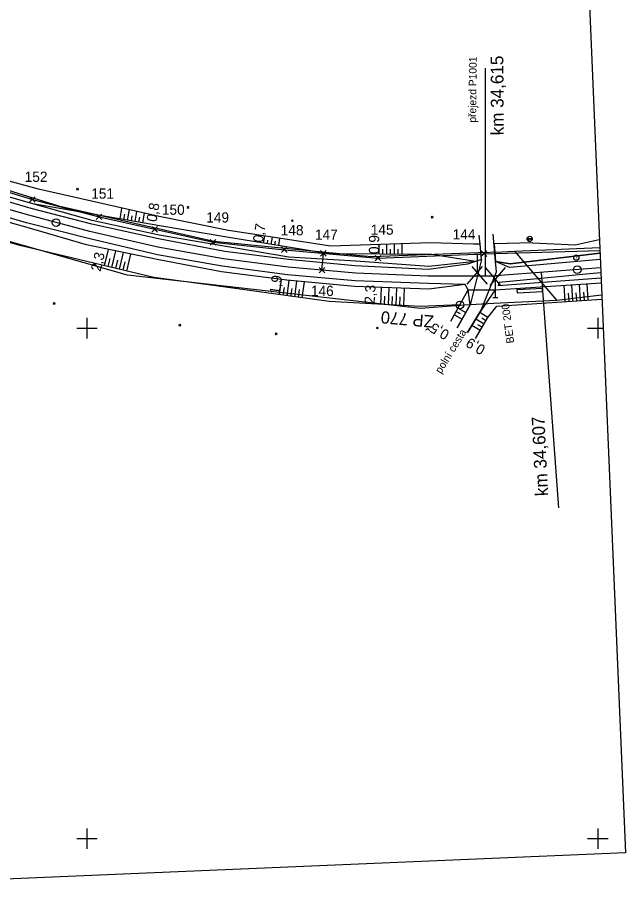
# Model space of a CAD drawing. Extents: x -806456 to -805395, y -1150847 to -1150506.
# Drawn here: x -805513.6 to -805394.6, y -1150811.7 to -1150639.2 of the extents above; entities that cross this region are included whole.
import ezdxf

# ---------------------------------------------------------------- set-up
doc = ezdxf.new("R2010")
doc.units = 0
for name, color, linetype in [('0381KM032-037P - Vrstva 1', 7, 'Continuous'), ('0381KM032-037P - Vrstva 19', 7, 'Continuous'), ('0381KM032-037P - Vrstva 36', 7, 'Continuous'), ('0381KM032-037P - Vrstva 4', 7, 'Continuous'), ('0381KM032-037P - Vrstva 48', 7, 'Continuous'), ('0381KM032-037P - Vrstva 49', 7, 'Continuous'), ('0381KM032-037P - Vrstva 51', 7, 'Continuous'), ('0381KM032-037P - Vrstva 55', 7, 'Continuous'), ('0381KM032-037P - Vrstva 7', 7, 'Continuous'), ('0381KM032-037P - Vrstva 9', 7, 'Continuous'), ('Default', 7, 'Continuous'), ('formát', 7, 'Continuous'), ('hran DP - hran DP', 7, 'Continuous'), ('krizky_1000 - Vrstva 1', 7, 'Continuous'), ('PSR_C2_2_Lomove_body_Vimperk - Vrstva 60', 7, 'Continuous'), ('PSR_C2_2_trasa_Vimperk - Kabelová trasa', 7, 'Continuous'), ('vyt_sit - stávající', 7, 'Continuous')]:
    doc.layers.add(name, color=color, linetype=linetype)

msp = doc.modelspace()

# ---------------------------------------------------------------- linework, layer by layer
at = {"layer": '0381KM032-037P - Vrstva 1'}
for points in [[(-805499.4, -1150681.08), (-805511.35, -1150677.89), (-805524.48, -1150674.12), (-805529.81, -1150672.54)], [(-805399.47, -1150688.2), (-805419.96, -1150689.78), (-805423.96, -1150689.8), (-805433.29, -1150689.8), (-805447.38, -1150689.21), (-805460.61, -1150688.07), (-805473.24, -1150686.41), (-805486.12, -1150684.11), (-805499.4, -1150681.08)]]:
    msp.add_lwpolyline(points, dxfattribs=at)
at = {"layer": '0381KM032-037P - Vrstva 19'}
msp.add_line((-805425.41, -1150692.47), (-805420.07, -1150692.47), dxfattribs=at)
at = {"layer": '0381KM032-037P - Vrstva 36'}
for p, q in [((-805413.84, -1150682.5), (-805412.84, -1150682.5)), ((-805412.84, -1150682.5), (-805413.84, -1150682.5)), ((-805413.28, -1150683), (-805413.77, -1150682.5)), ((-805412.94, -1150682.8), (-805413.24, -1150682.5))]:
    msp.add_line(p, q, dxfattribs=at)
msp.add_circle((-805413.34, -1150682.5), 0.503, dxfattribs=at)
msp.add_arc((-805413.34, -1150682.5), 0.503, 180, 0, dxfattribs=at)
at = {"layer": '0381KM032-037P - Vrstva 4'}
for p, q in [((-805421.99, -1150689.77), (-805421.99, -1150649.07)), ((-805423.11, -1150685.55), (-805424.11, -1150685.55)), ((-805423.61, -1150685.55), (-805423.61, -1150689.05)), ((-805422.61, -1150687.9), (-805425.61, -1150691.4)), ((-805421.61, -1150691.4), (-805424.61, -1150687.9)), ((-805422.05, -1150688.15), (-805419.05, -1150691.65)), ((-805421.05, -1150691.65), (-805418.05, -1150688.15)), ((-805423.96, -1150689.8), (-805419.82, -1150689.74)), ((-805420.05, -1150694), (-805420.05, -1150690.5)), ((-805420.55, -1150694), (-805419.55, -1150694))]:
    msp.add_line(p, q, dxfattribs=at)
for points in [[(-805485.85, -1150681.76), (-805498.96, -1150678.92), (-805510.6, -1150675.66), (-805525.22, -1150671.48), (-805544.53, -1150665.72), (-805562.31, -1150661.11), (-805574.56, -1150658.15), (-805590.74, -1150655.42), (-805602.22, -1150654.14), (-805617.62, -1150652.74), (-805630.08, -1150651.83), (-805647.65, -1150650.8), (-805688.26, -1150650.5)], [(-805423.97, -1150686.92), (-805425.51, -1150687.49), (-805433.17, -1150688.49), (-805447.58, -1150687.79), (-805460.54, -1150686.52), (-805473.03, -1150684.97), (-805486, -1150682.53), (-805499.06, -1150679.64), (-805510.93, -1150676.58), (-805525.41, -1150672.29), (-805545.14, -1150666.47), (-805562.36, -1150661.85), (-805574.71, -1150659.28), (-805590.7, -1150656.46), (-805602.42, -1150654.96), (-805617.57, -1150653.8), (-805630.08, -1150653.28), (-805647.6, -1150652.35), (-805687.98, -1150651.47)], [(-805425.98, -1150691.47), (-805433.13, -1150691.22), (-805447.47, -1150690.71), (-805460.74, -1150689.57), (-805473.54, -1150687.87), (-805486.2, -1150685.62), (-805499.7, -1150682.42), (-805511.82, -1150679.35), (-805526.11, -1150675.23), (-805545.84, -1150669.48), (-805563.16, -1150664.96), (-805575.57, -1150662.2), (-805590.62, -1150659.46), (-805602.86, -1150658.06), (-805617.64, -1150656.78), (-805630.16, -1150656.16), (-805647.73, -1150655.65), (-805688.15, -1150654.42)], [(-805425.41, -1150692.47), (-805425.98, -1150691.47), (-805433.11, -1150692.35), (-805447.61, -1150691.82), (-805460.9, -1150690.59), (-805473.67, -1150688.98), (-805486.26, -1150686.57), (-805500.08, -1150683.65), (-805512.15, -1150680.12), (-805526.27, -1150676.26), (-805545.98, -1150670.57), (-805563.42, -1150665.87), (-805575.79, -1150663.12), (-805590.93, -1150660.59), (-805603.28, -1150659.09), (-805617.92, -1150657.97), (-805630.11, -1150657.32), (-805646.66, -1150657.1), (-805648.58, -1150657.2), (-805687.42, -1150655.93)], [(-805423.97, -1150686.92), (-805433.1, -1150687.91), (-805447.34, -1150686.91), (-805460.49, -1150686.09), (-805485.85, -1150681.76)], [(-805399.6, -1150685.34), (-805417.14, -1150687.42), (-805420, -1150686.97)], [(-805399.54, -1150686.56), (-805417.27, -1150688.09), (-805420, -1150686.97)], [(-805399.43, -1150689.16), (-805401.63, -1150689.36), (-805419.33, -1150691.07), (-805419.49, -1150691.68)], [(-805399.39, -1150690.24), (-805419.49, -1150691.68)]]:
    msp.add_lwpolyline(points, dxfattribs=at)
at = {"layer": '0381KM032-037P - Vrstva 48'}
for p, q in [((-805493.52, -1150678.6), (-805493.15, -1150676.49)), ((-805492.78, -1150678.73), (-805492.6, -1150677.69)), ((-805492.04, -1150678.85), (-805491.69, -1150676.82)), ((-805491.3, -1150678.98), (-805491.13, -1150677.99)), ((-805490.56, -1150679.11), (-805490.22, -1150677.16)), ((-805489.82, -1150679.23), (-805489.66, -1150678.28)), ((-805489.08, -1150679.36), (-805488.76, -1150677.49)), ((-805465.41, -1150683.34), (-805465.19, -1150681.94)), ((-805464.67, -1150683.46), (-805464.56, -1150682.75)), ((-805463.93, -1150683.58), (-805463.7, -1150682.16)), ((-805463.19, -1150683.7), (-805463.07, -1150682.98)), ((-805462.45, -1150683.82), (-805462.22, -1150682.37)), ((-805441.32, -1150685.5), (-805441.3, -1150683.55)), ((-805439.82, -1150685.51), (-805439.8, -1150683.51)), ((-805438.32, -1150685.52), (-805438.3, -1150683.46)), ((-805496.56, -1150687.78), (-805495.8, -1150684.56)), ((-805495.1, -1150688.12), (-805494.33, -1150684.87)), ((-805493.64, -1150688.47), (-805492.86, -1150685.18)), ((-805442.82, -1150685.49), (-805442.8, -1150683.6)), ((-805442.07, -1150685.49), (-805442.06, -1150684.53)), ((-805440.57, -1150685.5), (-805440.56, -1150684.52)), ((-805439.07, -1150685.51), (-805439.06, -1150684.5)), ((-805495.83, -1150687.95), (-805495.45, -1150686.33)), ((-805494.37, -1150688.3), (-805493.98, -1150686.66)), ((-805492.91, -1150688.64), (-805492.52, -1150686.99)), ((-805492.18, -1150688.82), (-805491.39, -1150685.49)), ((-805462.31, -1150693.46), (-805461.89, -1150690.47)), ((-805461.56, -1150693.56), (-805461.35, -1150692.06)), ((-805460.82, -1150693.66), (-805460.4, -1150690.64)), ((-805459.33, -1150693.87), (-805458.91, -1150690.78)), ((-805457.85, -1150694.07), (-805457.41, -1150690.91)), ((-805442.5, -1150695.34), (-805442.32, -1150692.01)), ((-805441, -1150695.43), (-805440.82, -1150692.07)), ((-805439.5, -1150695.51), (-805439.32, -1150692.12)), ((-805438, -1150695.59), (-805437.82, -1150692.18)), ((-805406.38, -1150694.81), (-805406.59, -1150691.59)), ((-805404.88, -1150694.71), (-805405.09, -1150691.49)), ((-805403.39, -1150694.62), (-805403.59, -1150691.39)), ((-805401.89, -1150694.52), (-805402.09, -1150691.3)), ((-805460.08, -1150693.77), (-805459.86, -1150692.24)), ((-805458.59, -1150693.97), (-805458.38, -1150692.41)), ((-805441.75, -1150695.39), (-805441.66, -1150693.71)), ((-805440.25, -1150695.47), (-805440.16, -1150693.78)), ((-805438.75, -1150695.55), (-805438.66, -1150693.85)), ((-805405.63, -1150694.76), (-805405.73, -1150693.15)), ((-805404.13, -1150694.66), (-805404.24, -1150693.05)), ((-805402.64, -1150694.57), (-805402.74, -1150692.96)), ((-805428.08, -1150697.36), (-805426.58, -1150698.22)), ((-805427.71, -1150696.71), (-805426.96, -1150697.14)), ((-805427.34, -1150696.06), (-805425.83, -1150696.92)), ((-805421.51, -1150697.9), (-805423.11, -1150696.95)), ((-805422.27, -1150699.19), (-805423.9, -1150698.22)), ((-805421.89, -1150698.54), (-805422.7, -1150698.06)), ((-805423.04, -1150700.48), (-805424.68, -1150699.5)), ((-805422.66, -1150699.83), (-805423.47, -1150699.35))]:
    msp.add_line(p, q, dxfattribs=at)
at = {"layer": '0381KM032-037P - Vrstva 49'}
for p, q in [((-805501.66, -1150672.97), (-805502.01, -1150672.62)), ((-805501.66, -1150672.62), (-805502.01, -1150672.97)), ((-805480.06, -1150676.54), (-805480.41, -1150676.19)), ((-805480.06, -1150676.19), (-805480.41, -1150676.54)), ((-805432.26, -1150678.45), (-805432.61, -1150678.1)), ((-805432.26, -1150678.1), (-805432.61, -1150678.45)), ((-805459.62, -1150679.12), (-805459.97, -1150678.77)), ((-805459.62, -1150678.77), (-805459.97, -1150679.12)), ((-805426.99, -1150695.45), (-805425.41, -1150692.47)), ((-805506.23, -1150695.39), (-805506.58, -1150695.03)), ((-805506.23, -1150695.03), (-805506.58, -1150695.39)), ((-805481.65, -1150699.61), (-805482, -1150699.26)), ((-805481.65, -1150699.26), (-805482, -1150699.61)), ((-805442.98, -1150700.16), (-805443.33, -1150699.81)), ((-805442.98, -1150699.81), (-805443.33, -1150700.16)), ((-805462.79, -1150701.28), (-805463.14, -1150700.93)), ((-805462.79, -1150700.93), (-805463.14, -1150701.28))]:
    msp.add_line(p, q, dxfattribs=at)
for points in [[(-805423.97, -1150686.92), (-805433.1, -1150687.91), (-805447.34, -1150686.91), (-805460.49, -1150686.09), (-805485.85, -1150681.76), (-805498.96, -1150678.92), (-805510.6, -1150675.66), (-805525.22, -1150671.48), (-805544.53, -1150665.72), (-805562.31, -1150661.11), (-805571.99, -1150658.79), (-805574.56, -1150658.15), (-805590.74, -1150655.42), (-805602.22, -1150654.14), (-805617.62, -1150652.74), (-805630.08, -1150651.83), (-805647.65, -1150650.8), (-805688.26, -1150650.5)], [(-805424.36, -1150683.57), (-805432.74, -1150683.28), (-805452.35, -1150683.91), (-805462.43, -1150682.34), (-805472.3, -1150680.9), (-805485.84, -1150678.15), (-805509.51, -1150672.79), (-805524.62, -1150668.67), (-805544.15, -1150662.92), (-805562.19, -1150658.51), (-805574.34, -1150655.56), (-805587.56, -1150653.68), (-805602.19, -1150651.94)], [(-805425.41, -1150692.47), (-805425.98, -1150691.47), (-805433.11, -1150692.35), (-805447.61, -1150691.82), (-805460.9, -1150690.59), (-805473.67, -1150688.98), (-805486.26, -1150686.57), (-805500.08, -1150683.65), (-805512.15, -1150680.12), (-805526.27, -1150676.26), (-805545.98, -1150670.57), (-805563.42, -1150665.87), (-805575.79, -1150663.12), (-805590.93, -1150660.59), (-805603.28, -1150659.09), (-805617.92, -1150657.97), (-805630.11, -1150657.32), (-805646.15, -1150657.11), (-805646.27, -1150657.1), (-805646.57, -1150657.13), (-805646.66, -1150657.1), (-805648.58, -1150657.2), (-805687.42, -1150655.93)], [(-805428.8, -1150698.61), (-805426.99, -1150695.45), (-805434.79, -1150695.76), (-805452.59, -1150694.8), (-805474.79, -1150691.73), (-805486.9, -1150690.07), (-805513.13, -1150683.83), (-805526.69, -1150679.91), (-805538.18, -1150675.92), (-805547.05, -1150672.92), (-805563.97, -1150668.42), (-805576.87, -1150665.35), (-805586.81, -1150663.24), (-805590.73, -1150662.74), (-805601.92, -1150661.35), (-805629.88, -1150659.22), (-805648.74, -1150658.99), (-805687.58, -1150660.02)], [(-805422.8, -1150686.53), (-805423.97, -1150686.92), (-805432.55, -1150685.56), (-805452.56, -1150685.41), (-805472.6, -1150682.19), (-805485.72, -1150679.94), (-805510.6, -1150675.66)], [(-805422.8, -1150686.53), (-805423.05, -1150683.54), (-805424.36, -1150683.57)], [(-805412.74, -1150683.31), (-805420.31, -1150683.48), (-805420, -1150686.97)], [(-805412.74, -1150683.31), (-805404.41, -1150683.71), (-805399.71, -1150682.62)], [(-805420, -1150686.97), (-805417.14, -1150687.42), (-805399.6, -1150685.34)], [(-805420.07, -1150692.47), (-805399.35, -1150691.12)], [(-805427.56, -1150699.92), (-805424.99, -1150695.46), (-805425.41, -1150692.47)], [(-805420.07, -1150692.47), (-805422.84, -1150696.5), (-805425.52, -1150700.88)], [(-805419.74, -1150695.67), (-805399.21, -1150694.35)], [(-805423.96, -1150702.03), (-805421.5, -1150697.89), (-805419.74, -1150695.67)]]:
    msp.add_lwpolyline(points, dxfattribs=at)
at = {"layer": '0381KM032-037P - Vrstva 51'}
for points in [[(-805425.52, -1150700.88), (-805422.84, -1150696.5), (-805419.83, -1150688.97), (-805420, -1150686.97), (-805420.48, -1150681.6)], [(-805422.8, -1150686.53), (-805423.05, -1150683.54), (-805423.2, -1150681.79)], [(-805422.8, -1150686.53), (-805424.99, -1150695.46), (-805427.56, -1150699.92)]]:
    msp.add_lwpolyline(points, dxfattribs=at)
at = {"layer": '0381KM032-037P - Vrstva 55'}
msp.add_line((-805416.34, -1150684.94), (-805408.01, -1150694.56), dxfattribs=at)
at = {"layer": '0381KM032-037P - Vrstva 7'}
msp.add_line((-805404.26, -1150686.19), (-805404.16, -1150686.19), dxfattribs=at)
for centre, radius in [((-805506.04, -1150679.31), 0.75), ((-805404.21, -1150686.19), 0.5), ((-805404.03, -1150688.55), 0.75)]:
    msp.add_circle(centre, radius, dxfattribs=at)
at = {"layer": '0381KM032-037P - Vrstva 9'}
for p, q in [((-805411.08, -1150689.08), (-805407.73, -1150735.22)), ((-805410.84, -1150692.23), (-805410.86, -1150691.64)), ((-805410.84, -1150692.23), (-805415.83, -1150692.47)), ((-805415.83, -1150692.47), (-805415.8, -1150693.06)), ((-805415.8, -1150693.06), (-805410.81, -1150692.82)), ((-805410.81, -1150692.82), (-805410.84, -1150692.23))]:
    msp.add_line(p, q, dxfattribs=at)
at = {"layer": 'formát'}
for p, q in [((-805407.21, -1150506.06), (-805394.61, -1150802.8)), ((-805394.61, -1150802.8), (-805604.42, -1150811.7))]:
    msp.add_line(p, q, dxfattribs=at)
at = {"layer": 'hran DP - hran DP'}
for p, q in [((-805522.57, -1150670.78), (-805505.56, -1150676.07)), ((-805505.56, -1150676.07), (-805488.96, -1150679.81)), ((-805492.06, -1150689.65), (-805525.6, -1150680.1)), ((-805488.96, -1150679.81), (-805475.13, -1150682.93)), ((-805475.13, -1150682.93), (-805447.24, -1150685.68)), ((-805433.7, -1150685.59), (-805423.42, -1150685.2)), ((-805423.42, -1150685.2), (-805418.81, -1150685.03)), ((-805418.81, -1150685.03), (-805416.34, -1150684.94)), ((-805416.34, -1150684.94), (-805399.64, -1150684.18)), ((-805447.24, -1150685.68), (-805444.22, -1150685.98)), ((-805444.22, -1150685.98), (-805433.7, -1150685.59)), ((-805434.71, -1150696.14), (-805492.06, -1150689.65)), ((-805399.25, -1150693.56), (-805408.01, -1150694.56)), ((-805426.08, -1150695.49), (-805434.71, -1150696.14)), ((-805420.42, -1150695.2), (-805426.08, -1150695.49)), ((-805408.01, -1150694.56), (-805420.42, -1150695.2))]:
    msp.add_line(p, q, dxfattribs=at)
at = {"layer": 'krizky_1000 - Vrstva 1'}
for points in [[(-805500, -1150698), (-805500, -1150702)], [(-805400, -1150698), (-805400, -1150702)], [(-805502, -1150700), (-805498, -1150700)], [(-805402, -1150700), (-805398.97, -1150700)], [(-805500, -1150798), (-805500, -1150802)], [(-805400, -1150798), (-805400, -1150802)], [(-805502, -1150800), (-805498, -1150800)], [(-805402, -1150800), (-805398, -1150800)]]:
    msp.add_lwpolyline(points, dxfattribs=at)
at = {"layer": 'PSR_C2_2_Lomove_body_Vimperk - Vrstva 60'}
for p, q in [((-805511.23, -1150675.35), (-805510.13, -1150674.25)), ((-805510.13, -1150675.35), (-805511.23, -1150674.25)), ((-805498.17, -1150678.74), (-805497.07, -1150677.64)), ((-805497.07, -1150678.74), (-805498.17, -1150677.64)), ((-805487.27, -1150681.18), (-805486.17, -1150680.08)), ((-805486.17, -1150681.18), (-805487.27, -1150680.08)), ((-805475.86, -1150683.73), (-805474.76, -1150682.63)), ((-805474.76, -1150683.73), (-805475.86, -1150682.63)), ((-805461.9, -1150685.2), (-805460.8, -1150684.1)), ((-805460.8, -1150685.2), (-805461.9, -1150684.1)), ((-805454.27, -1150685.88), (-805453.17, -1150684.78)), ((-805453.17, -1150685.88), (-805454.27, -1150684.78)), ((-805422.82, -1150685.97), (-805421.72, -1150684.87)), ((-805421.72, -1150685.97), (-805422.82, -1150684.87)), ((-805443.6, -1150686.84), (-805442.5, -1150685.74)), ((-805442.5, -1150686.84), (-805443.6, -1150685.74)), ((-805454.55, -1150689.19), (-805453.45, -1150688.09)), ((-805453.45, -1150689.19), (-805454.55, -1150688.09))]:
    msp.add_line(p, q, dxfattribs=at)
at = {"layer": 'PSR_C2_2_trasa_Vimperk - Kabelová trasa'}
msp.add_line((-805453.99, -1150688.64), (-805453.72, -1150685.33), dxfattribs=at)
for points in [[(-805624.23, -1150651.13), (-805607.21, -1150652.21), (-805573.59, -1150656.97), (-805547.17, -1150663.21), (-805524.75, -1150670.52), (-805510.68, -1150674.8), (-805497.62, -1150678.19), (-805486.72, -1150680.63), (-805475.31, -1150683.18), (-805461.35, -1150684.65), (-805443.05, -1150686.29), (-805422.27, -1150685.42)], [(-805422.27, -1150685.42), (-805399.62, -1150684.81)]]:
    msp.add_lwpolyline(points, dxfattribs=at)
at = {"layer": 'vyt_sit - stávající'}
msp.add_line((-805427.04, -1150695.45), (-805426.94, -1150695.45), dxfattribs=at)
msp.add_circle((-805426.99, -1150695.45), 0.756, dxfattribs=at)

# ---------------------------------------------------------------- texts
at = {"layer": '0381KM032-037P - Vrstva 19'}
msp.add_text('BET 200', height=1.5, rotation=97.5063, dxfattribs=at).set_placement((-805416.36, -1150702.88))
at = {"layer": '0381KM032-037P - Vrstva 4'}
for s, height, rotation, p in [('přejezd P1001', 1.5, 89.4547, (-805423.83, -1150659.74)), ('km 34,615', 2.5, 90.3142, (-805418.41, -1150662.22))]:
    msp.add_text(s, height=height, rotation=rotation, dxfattribs=at).set_placement(p)
at = {"layer": '0381KM032-037P - Vrstva 48'}
for s, rotation, p in [('0,8', 80.2414, (-805486.4, -1150679.29)), ('0,7', 80.8528, (-805465.58, -1150683.35)), ('0,9', 89.5678, (-805442.82, -1150685.49)), ('2,3', 76.6332, (-805497.34, -1150689.02)), ('1,9', 82.1252, (-805462.31, -1150693.46)), ('2,3', 86.8943, (-805443.69, -1150695.28)), ('0,5', 150.2278, (-805428.88, -1150700.69)), ('0,9', 149.2587, (-805421.83, -1150703.66))]:
    msp.add_text(s, height=2, rotation=rotation, dxfattribs=at).set_placement(p)
at = {"layer": '0381KM032-037P - Vrstva 51'}
msp.add_text('polní cesta', height=1.5, rotation=58.5387, dxfattribs=at).set_placement((-805430.69, -1150709.03))
at = {"layer": '0381KM032-037P - Vrstva 9'}
msp.add_text('km 34,607', height=2.5, rotation=92.7706, dxfattribs=at).set_placement((-805409.71, -1150732.84))
at = {"layer": 'Default'}
for s, p in [('152', (-805512.18, -1150671.35)), ('151', (-805499.16, -1150674.63)), ('150', (-805485.33, -1150677.79)), ('149', (-805476.65, -1150679.31)), ('148', (-805462.07, -1150681.81)), ('145', (-805444.44, -1150681.7)), ('147', (-805455.37, -1150682.69)), ('144', (-805428.41, -1150682.63)), ('146', (-805456.16, -1150693.7))]:
    msp.add_text(s, height=2, dxfattribs=at).set_placement(p)
at = {"layer": 'vyt_sit - stávající'}
msp.add_text('ŽP 770', height=2.4, rotation=175, dxfattribs=at).set_placement((-805432.05, -1150697.54))

doc.saveas('drawing.dxf')
